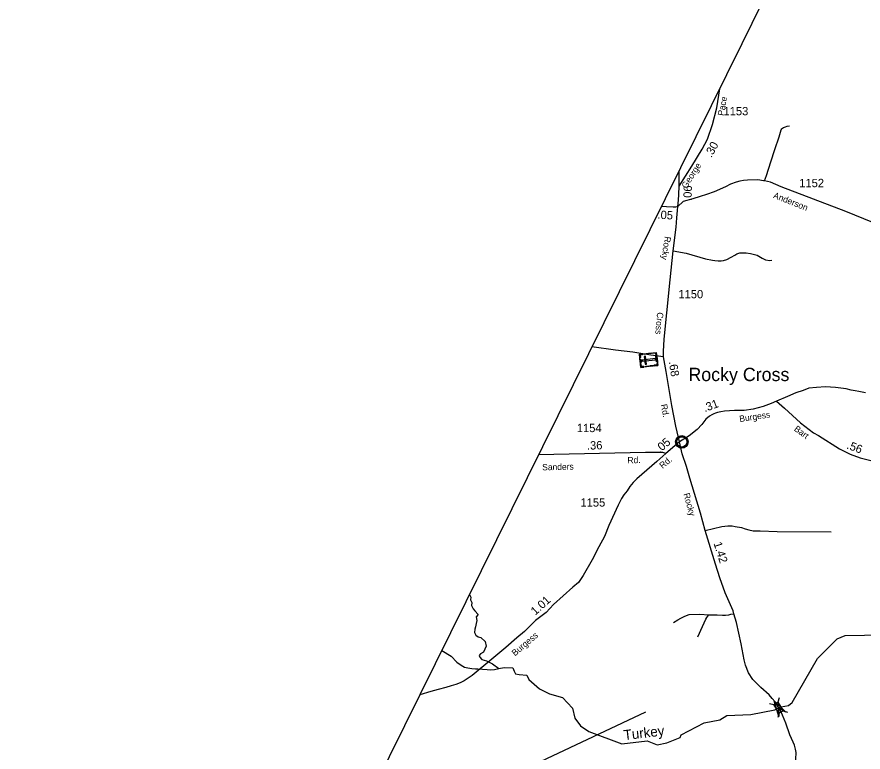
# Model space of a CAD drawing. Extents: x 2220236 to 2384410, y 720751 to 894131.
# Drawn here: x 2220576 to 2233278, y 765352 to 776386 of the extents above; entities that cross this region are included whole.
import ezdxf

# ---------------------------------------------------------------- set-up
doc = ezdxf.new("R2010")
doc.units = 0
doc.layers.add('Default', color=7, linetype='Continuous')

msp = doc.modelspace()

# ---------------------------------------------------------------- linework, layer by layer
at = {"layer": 'Default'}
for p, q in [((2230516, 773844), (2230516, 774074)), ((2230520, 770009), (2230316, 769832)), ((2232017, 766168), (2232000, 766101)), ((2231872, 766083), (2231939, 766065)), ((2232076, 765971), (2232143, 765953)), ((2232017, 765936), (2232000, 765869))]:
    msp.add_line(p, q, dxfattribs=at)
for points in [[(2293118, 894131), (2291904, 891776), (2258822, 829665), (2255410, 823324), (2242089, 797599), (2231460, 775981), (2225011, 762953), (2220576, 753519)], [(2230516, 773844), (2230705, 774144), (2230862, 774403), (2230945, 774553), (2231016, 774771), (2231083, 775022), (2231127, 775308)], [(2231799, 773924), (2231829, 774005), (2231893, 774209), (2231955, 774397), (2232017, 774587), (2232036, 774659), (2232050, 774694), (2232059, 774707), (2232069, 774717), (2232085, 774725), (2232112, 774736), (2232139, 774746), (2232176, 774752)], [(2233562, 773248), (2233021, 773465), (2232050, 773838), (2231887, 773906), (2231799, 773924), (2231782, 773928), (2231698, 773940), (2231542, 773937), (2231484, 773933), (2231430, 773923), (2231372, 773906), (2231288, 773874), (2231211, 773834), (2231043, 773763), (2230926, 773723), (2230832, 773692), (2230723, 773656), (2230579, 773614), (2230496, 773541)], [(2230496, 773541), (2230505, 773636), (2230512, 773720), (2230516, 773844)], [(2230496, 773541), (2230461, 773532), (2230427, 773532), (2230328, 773538), (2230251, 773540)], [(2230520, 770009), (2230466, 770246), (2230407, 770554), (2230321, 771064), (2230284, 771284), (2230284, 771363), (2230292, 771551), (2230331, 771947), (2230380, 772442), (2230425, 772876), (2230473, 773233), (2230484, 773370), (2230494, 773483), (2230496, 773541)], [(2230425, 772876), (2230620, 772839), (2230915, 772757), (2231016, 772735), (2231054, 772730), (2231102, 772724), (2231147, 772724), (2231185, 772728), (2231234, 772744), (2231296, 772780), (2231354, 772811), (2231381, 772832), (2231428, 772844), (2231482, 772846), (2231525, 772844), (2231586, 772834), (2231688, 772808), (2231763, 772763), (2231813, 772742), (2231880, 772730), (2231906, 772735)], [(2230284, 771284), (2230092, 771309), (2229822, 771353), (2229562, 771383), (2229208, 771432)], [(2233316, 770744), (2233212, 770763), (2233160, 770775), (2233099, 770786), (2233023, 770803), (2232863, 770826), (2232714, 770832), (2232578, 770826), (2232465, 770812), (2232377, 770781), (2232270, 770744), (2232143, 770691), (2231978, 770620)], [(2231978, 770620), (2231900, 770586), (2231777, 770537), (2231629, 770500), (2231494, 770479), (2231349, 770479), (2231196, 770468), (2231142, 770458), (2231120, 770454), (2231094, 770449), (2231061, 770439), (2231038, 770430), (2231010, 770416), (2230972, 770392), (2230917, 770348), (2230859, 770271), (2230785, 770196), (2230669, 770101), (2230520, 770009)], [(2231978, 770620), (2232099, 770513), (2232340, 770295), (2232534, 770145), (2232611, 770106), (2232922, 769904), (2233085, 769821), (2233234, 769766), (2233417, 769725), (2233478, 769707), (2234607, 769462)], [(2232001, 766033), (2231986, 766056), (2231957, 766104), (2231915, 766158), (2231869, 766209), (2231744, 766320), (2231622, 766441), (2231556, 766540), (2231515, 766658), (2231495, 766738), (2231447, 766978), (2231378, 767299), (2231337, 767427), (2231327, 767474), (2231206, 767744), (2231128, 767969), (2231063, 768174), (2230907, 768676), (2230835, 768936), (2230749, 769232), (2230675, 769462), (2230626, 769636), (2230564, 769829), (2230520, 770009)], [(2230316, 769832), (2230180, 769712), (2230034, 769585), (2229881, 769454), (2229826, 769399), (2229778, 769339), (2229737, 769275), (2229687, 769214), (2229654, 769158), (2229600, 769060), (2229463, 768753), (2229394, 768588), (2229310, 768434), (2229209, 768235), (2229075, 768002), (2229004, 767895), (2228921, 767827), (2228632, 767567), (2228520, 767446), (2228362, 767325), (2228195, 767161), (2228079, 767068), (2227915, 766923), (2227647, 766695), (2227470, 766553), (2227412, 766501), (2227289, 766422), (2227229, 766393), (2227164, 766365), (2227094, 766346), (2227014, 766322), (2226898, 766289), (2226788, 766262), (2226624, 766213)], [(2230316, 769832), (2230270, 769846), (2230013, 769850), (2228406, 769812)], [(2230907, 768676), (2231158, 768736), (2231246, 768747), (2231314, 768748), (2231360, 768736), (2231452, 768721), (2231506, 768703), (2231563, 768688), (2231627, 768672), (2231677, 768671), (2231735, 768673), (2231987, 768665), (2232800, 768656)], [(2227370, 767719), (2227391, 767679), (2227385, 767637), (2227407, 767598), (2227398, 767552), (2227398, 767552), (2227424, 767504), (2227450, 767471), (2227499, 767416), (2227472, 767383), (2227479, 767328), (2227469, 767283), (2227459, 767234), (2227450, 767198), (2227446, 767149), (2227463, 767107), (2227498, 767081), (2227541, 767071), (2227606, 767010), (2227622, 766941), (2227579, 766850), (2227535, 766825), (2227516, 766803), (2227525, 766774), (2227557, 766740), (2227626, 766719), (2227714, 766675), (2227809, 766605)], [(2230430, 767295), (2230498, 767336), (2230542, 767364), (2230593, 767386), (2230626, 767400), (2230665, 767416), (2230827, 767421), (2230964, 767411)], [(2230796, 767080), (2230869, 767235), (2230916, 767345), (2230931, 767372), (2230964, 767411)], [(2230964, 767411), (2231026, 767412), (2231090, 767412), (2231169, 767407), (2231211, 767408), (2231265, 767412), (2231291, 767420), (2231337, 767427)], [(2227809, 766605), (2227891, 766621), (2228019, 766614), (2228038, 766566), (2228062, 766526), (2228116, 766514), (2228232, 766508), (2228258, 766440), (2228422, 766300), (2228573, 766225), (2228764, 766172), (2228918, 766009), (2228953, 765861), (2229037, 765744), (2229163, 765663), (2229656, 765475), (2230039, 765520), (2230189, 765461), (2230330, 765488), (2230530, 765572), (2230546, 765608), (2230894, 765791), (2231127, 765835), (2231235, 765902), (2231593, 765914), (2231952, 765987), (2232008, 766017), (2232048, 766030), (2232161, 766050), (2232216, 766095), (2232594, 766757), (2232891, 767049), (2233008, 767102), (2233591, 767113)], [(2226952, 766874), (2227094, 766790), (2227178, 766699), (2227247, 766657), (2227295, 766628), (2227347, 766618), (2227403, 766608), (2227458, 766602), (2227497, 766599), (2227633, 766592), (2227692, 766586), (2227744, 766592), (2227809, 766605)], [(2232160, 762906), (2232123, 764614), (2232158, 764760), (2232182, 764889), (2232261, 765157), (2232270, 765243), (2232272, 765345), (2232269, 765369), (2232263, 765397), (2232247, 765453), (2232228, 765501), (2232181, 765608), (2232120, 765784), (2232069, 765905), (2232043, 765964), (2232001, 766033)], [(2230014, 765951), (2226954, 764510), (2225415, 763770)]]:
    msp.add_lwpolyline(points, dxfattribs=at)
for points in [[(2229944, 771124), (2229921, 771322), (2230174, 771351), (2230197, 771153)], [(2229964, 771327), (2229966, 771316), (2229934, 771312), (2229938, 771272), (2229927, 771271), (2229921, 771322)], [(2230038, 771324), (2229995, 771319), (2229994, 771331), (2230037, 771335)], [(2230104, 771332), (2230061, 771327), (2230059, 771338), (2230102, 771343)], [(2230178, 771318), (2230167, 771317), (2230164, 771339), (2230124, 771334), (2230123, 771345), (2230174, 771351)], [(2229935, 771198), (2229929, 771250), (2229941, 771251), (2229947, 771199)], [(2229987, 771129), (2229985, 771141), (2229953, 771137), (2229949, 771177), (2229938, 771176), (2229944, 771124)], [(2229960, 771236), (2229963, 771218), (2230164, 771240), (2230162, 771259)], [(2230007, 771173), (2230025, 771175), (2230012, 771292), (2229993, 771290)], [(2230193, 771186), (2230181, 771185), (2230184, 771163), (2230144, 771158), (2230145, 771147), (2230197, 771153)], [(2230179, 771209), (2230169, 771293), (2230181, 771295), (2230190, 771210)], [(2230060, 771138), (2230017, 771133), (2230016, 771144), (2230059, 771149)], [(2230127, 771145), (2230084, 771140), (2230083, 771152), (2230126, 771157)], [(2230480, 770019), (2230481, 770025), (2230483, 770031), (2230485, 770039), (2230488, 770044), (2230492, 770050), (2230495, 770055), (2230499, 770060), (2230504, 770064), (2230510, 770069), (2230515, 770072), (2230520, 770075), (2230525, 770078), (2230530, 770080), (2230536, 770082), (2230540, 770083), (2230545, 770084), (2230549, 770084), (2230556, 770085), (2230560, 770085), (2230566, 770084), (2230571, 770084), (2230576, 770083), (2230581, 770081), (2230586, 770079), (2230592, 770076), (2230599, 770073), (2230604, 770069), (2230609, 770065), (2230612, 770062), (2230616, 770058), (2230620, 770053), (2230623, 770049), (2230626, 770044), (2230629, 770038), (2230631, 770033), (2230632, 770028), (2230634, 770024), (2230635, 770018), (2230635, 770013), (2230636, 770007), (2230636, 770001), (2230635, 769996), (2230634, 769990), (2230632, 769984), (2230631, 769978), (2230628, 769973), (2230625, 769967), (2230622, 769962), (2230618, 769957), (2230614, 769952), (2230609, 769947), (2230604, 769943), (2230599, 769940), (2230594, 769937), (2230588, 769934), (2230581, 769931), (2230575, 769930), (2230568, 769928), (2230564, 769928), (2230559, 769928), (2230553, 769928), (2230549, 769928), (2230544, 769929), (2230538, 769930), (2230533, 769931), (2230528, 769933), (2230523, 769935), (2230519, 769938), (2230513, 769942), (2230507, 769946), (2230502, 769950), (2230498, 769955), (2230494, 769959), (2230491, 769963), (2230487, 769971), (2230486, 769974), (2230484, 769978), (2230481, 769986), (2230480, 769993), (2230479, 769998), (2230479, 770005), (2230479, 770010), (2230479, 770016)], [(2232000, 766101), (2232077, 765971), (2232016, 765935), (2231939, 766065)], [(2232012, 765887), (2231945, 766122), (2232120, 765952), (2232008, 766017)]]:
    msp.add_lwpolyline(points, close=True, dxfattribs=at)
for radius in [94.3, 76.7]:
    msp.add_circle((2230557, 770007), radius, dxfattribs=at)

# ---------------------------------------------------------------- texts
for s, height, rotation, p in [('Pace', 95, 80.4626, (2231189, 774897)), ('.30', 125, 61.0542, (2231001, 774266)), ('George', 95, 57.1506, (2230625, 773802)), ('.06', 125, 88.2643, (2230703, 773623)), ('Anderson', 95, 338.3571, (2231922, 773673)), ('.05', 125, 356.6625, (2230189, 773358)), ('Rocky', 95, 261.2458, (2230302, 773097)), ('Cross', 95, 265.1238, (2230187, 771957)), ('.68', 125, 279.5903, (2230360, 771209)), ('Rd.', 95, 281.5399, (2230240, 770565)), ('.31', 125, 20.4107, (2230903, 770453)), ('Burgess', 95, 8.5956, (2231428, 770305)), ('Bart', 95, 323.5418, (2232233, 770184)), ('.05', 125, 41.021, (2230224, 769834)), ('.36', 125, 1.3541, (2229134, 769891)), ('.56', 125, 339.5783, (2233022, 769911)), ('Rd.', 95, 1.399, (2229742, 769685)), ('Rd.', 95, 39.553, (2230268, 769601)), ('Sanders', 95, 1.399, (2228462, 769580)), ('Rocky', 95, 285.5566, (2230580, 769226)), ('1.42', 125, 287.5571, (2231032, 768486)), ('1.01', 125, 42.4101, (2228358, 767398)), ('Burgess', 95, 40.3913, (2228053, 766787)), ('Turkey', 150, 6.6496, (2229693, 765531))]:
    msp.add_text(s, height=height, rotation=rotation, dxfattribs=at).set_placement(p)
for s, height, p in [('1153', 125, (2231183, 774910)), ('1152', 125, (2232320, 773831)), ('1150', 125, (2230506, 772163)), ('Rocky Cross', 200, (2230656, 770920)), ('1154', 125, (2228981, 770154)), ('1155', 125, (2229036, 769036))]:
    msp.add_text(s, height=height, dxfattribs=at).set_placement(p)

doc.saveas('drawing.dxf')
